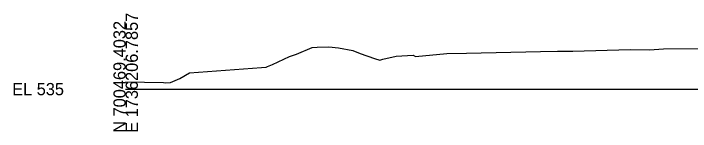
# Model space of a CAD drawing. Extents: x -26 to 803, y -10 to 646.
# Drawn here: x 474.3 to 629.4, y 590.3 to 617.3 of the extents above; entities that cross this region are included whole.
import ezdxf

# ---------------------------------------------------------------- set-up
doc = ezdxf.new("R2010")
doc.units = 0
for name, color, linetype in [('Default', 7, 'Continuous'), ('Exist Cross Section Cell', 7, 'Continuous'), ('Exist XS Ground Line', 7, 'Continuous')]:
    doc.layers.add(name, color=color, linetype=linetype)

msp = doc.modelspace()

# ---------------------------------------------------------------- linework, layer by layer
at = {"layer": 'Exist Cross Section Cell'}
msp.add_line((500, 600), (650, 600), dxfattribs=at)
at = {"layer": 'Exist XS Ground Line'}
for p, q in [((539.18, 608), (542.71, 609.52)), ((542.71, 609.52), (543.87, 609.6)), ((543.87, 609.6), (546.54, 609.68)), ((546.54, 609.68), (548.81, 609.45)), ((548.81, 609.45), (552.08, 608.86)), ((552.08, 608.86), (553.72, 608.15)), ((553.72, 608.15), (557.05, 607.02)), ((566.44, 607.45), (573.59, 608.17)), ((573.59, 608.17), (578.12, 608.22)), ((578.12, 608.22), (595.07, 608.63)), ((595.07, 608.63), (599, 608.65)), ((599, 608.65), (602.47, 608.68)), ((602.47, 608.68), (615.63, 609.09)), ((615.63, 609.09), (620.06, 609.01)), ((620.06, 609.01), (623.24, 609.22)), ((623.24, 609.22), (637.09, 609.32)), ((533.62, 605.62), (537.57, 607.44)), ((537.57, 607.44), (539.18, 608)), ((557.05, 607.02), (558.28, 606.61)), ((558.28, 606.61), (558.92, 606.82)), ((558.92, 606.82), (562.02, 607.57)), ((562.02, 607.57), (565.91, 607.75)), ((565.91, 607.75), (566.44, 607.45)), ((531.11, 604.98), (532.17, 605.06)), ((532.17, 605.06), (532.51, 605.2)), ((532.51, 605.2), (532.89, 605.35)), ((532.89, 605.35), (533.62, 605.62)), ((512.39, 602.42), (514.63, 603.76)), ((514.63, 603.76), (531.11, 604.98)), ((510.26, 601.51), (512.39, 602.42)), ((500, 601.64), (508.67, 601.48)), ((508.67, 601.48), (509.23, 601.47)), ((509.23, 601.47), (510.26, 601.51))]:
    msp.add_line(p, q, dxfattribs=at)

# ---------------------------------------------------------------- texts
at = {"layer": 'Default'}
msp.add_text('-', height=0.0001, dxfattribs=at).set_placement((500, 600))
msp.add_text('-', height=0.0001, dxfattribs=at).set_placement((500, 600))
at = {"layer": 'Exist Cross Section Cell'}
for s, p in [('E 1736206.7857', (502.8, 590)), ('N 700469.4032', (500, 590))]:
    msp.add_text(s, height=2.8, rotation=90, dxfattribs=at).set_placement(p)
msp.add_text('EL 535', height=2.8, dxfattribs=at).set_placement((474, 598.6))

doc.saveas('drawing.dxf')
